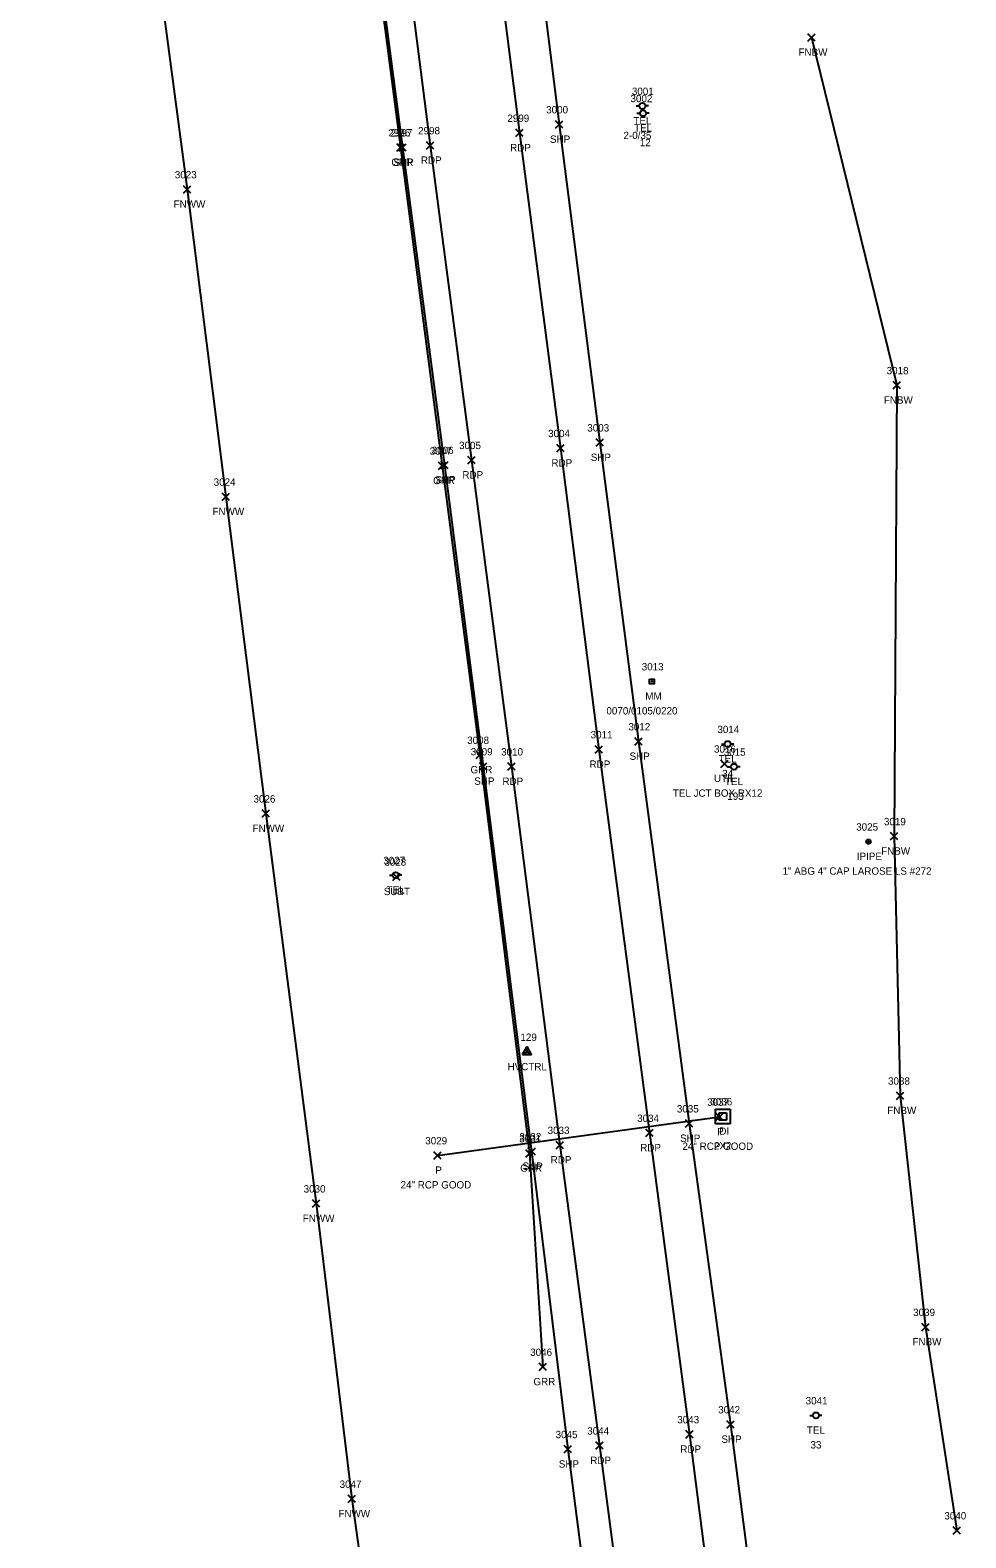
# Model space of a CAD drawing. Extents: x 1443071 to 1445292, y 614024 to 622563.
# Drawn here: x 1444081.8 to 1444336.5, y 617614.4 to 618024.6 of the extents above; entities that cross this region are included whole.
import ezdxf

# ---------------------------------------------------------------- set-up
doc = ezdxf.new("R2010")
doc.units = 0
for name, color, linetype in [('C_A', 7, 'Continuous'), ('C_I', 7, 'Continuous'), ('CPSM', 7, 'Continuous'), ('D_A', 7, 'Continuous'), ('D_C', 7, 'Continuous'), ('D_I', 7, 'Continuous'), ('D_TIC', 7, 'Continuous'), ('DCP', 7, 'Continuous'), ('DS', 7, 'Continuous'), ('L_A', 7, 'Continuous'), ('L_I', 7, 'Continuous'), ('L_TIC', 7, 'Continuous'), ('LFNC', 7, 'Continuous'), ('M_A', 7, 'Continuous'), ('M_C', 7, 'Continuous'), ('M_I', 7, 'Continuous'), ('MPIP', 7, 'Continuous'), ('P_A', 7, 'Continuous'), ('P_I', 7, 'Continuous'), ('P_TIC', 7, 'Continuous'), ('PET', 7, 'Continuous'), ('PSP', 7, 'Continuous'), ('R_A', 7, 'Continuous'), ('R_I', 7, 'Continuous'), ('R_TIC', 7, 'Continuous'), ('RGR', 7, 'Continuous'), ('S_A', 7, 'Continuous'), ('S_C', 7, 'Continuous'), ('S_I', 7, 'Continuous'), ('SRM', 7, 'Continuous'), ('U_A', 7, 'Continuous'), ('U_C', 7, 'Continuous'), ('U_I', 7, 'Continuous'), ('U_TIC', 7, 'Continuous'), ('UDEFAULT', 7, 'Continuous'), ('UP', 7, 'Continuous')]:
    doc.layers.add(name, color=color, linetype=linetype)

msp = doc.modelspace()

# ---------------------------------------------------------------- linework, layer by layer
at = {"layer": 'CPSM'}
for p, q in [((1444215.83, 617745.86), (1444217.08, 617748.02)), ((1444215.83, 617745.86), (1444217.08, 617746.58)), ((1444218.33, 617745.86), (1444217.08, 617748.02)), ((1444217.08, 617746.58), (1444217.08, 617748.02)), ((1444217.08, 617746.58), (1444217.08, 617746.58)), ((1444217.08, 617746.58), (1444218.33, 617745.86)), ((1444215.83, 617745.86), (1444218.33, 617745.86))]:
    msp.add_line(p, q, dxfattribs=at)
at = {"layer": 'D_TIC'}
for points in [[(1444268.44, 617727.93), (1444270.44, 617729.93)], [(1444270.44, 617727.93), (1444268.44, 617729.93)], [(1444191.73, 617717.43), (1444193.73, 617719.43)], [(1444193.73, 617717.43), (1444191.73, 617719.43)]]:
    msp.add_lwpolyline(points, dxfattribs=at)
at = {"layer": 'DCP'}
msp.add_lwpolyline([(1444192.73, 617718.43), (1444269.44, 617728.93)], dxfattribs=at)
at = {"layer": 'DS'}
for p, q in [((1444268.35, 617731.05), (1444272.35, 617731.05)), ((1444268.35, 617727.05), (1444268.35, 617731.05)), ((1444269.35, 617728.05), (1444269.35, 617730.05)), ((1444269.35, 617730.05), (1444271.35, 617730.05)), ((1444271.35, 617730.05), (1444271.35, 617728.05)), ((1444272.35, 617731.05), (1444272.35, 617727.05)), ((1444272.35, 617727.05), (1444268.35, 617727.05)), ((1444271.35, 617728.05), (1444269.35, 617728.05)), ((1444270.35, 617729.05), (1444270.35, 617729.05)), ((1444270.35, 617729.05), (1444270.35, 617729.05))]:
    msp.add_line(p, q, dxfattribs=at)
at = {"layer": 'L_TIC'}
for points in [[(1444293.48, 618021.6), (1444295.48, 618023.6)], [(1444295.48, 618021.6), (1444293.48, 618023.6)], [(1444123.56, 617980.26), (1444125.56, 617982.26)], [(1444125.56, 617980.26), (1444123.56, 617982.26)], [(1444316.71, 617926.96), (1444318.71, 617928.96)], [(1444318.71, 617926.96), (1444316.71, 617928.96)], [(1444134.13, 617896.63), (1444136.13, 617898.63)], [(1444136.13, 617896.63), (1444134.13, 617898.63)], [(1444145.03, 617810.43), (1444147.03, 617812.43)], [(1444147.03, 617810.43), (1444145.03, 617812.43)], [(1444315.98, 617804.26), (1444317.98, 617806.26)], [(1444317.98, 617804.26), (1444315.98, 617806.26)], [(1444317.65, 617733.67), (1444319.65, 617735.67)], [(1444319.65, 617733.67), (1444317.65, 617735.67)], [(1444158.7, 617704.33), (1444160.7, 617706.33)], [(1444160.7, 617704.33), (1444158.7, 617706.33)], [(1444324.49, 617670.72), (1444326.49, 617672.72)], [(1444326.49, 617670.72), (1444324.49, 617672.72)], [(1444168.41, 617623.98), (1444170.41, 617625.98)], [(1444170.41, 617623.98), (1444168.41, 617625.98)], [(1444333.07, 617615.38), (1444335.07, 617617.38)], [(1444335.07, 617615.38), (1444333.07, 617617.38)]]:
    msp.add_lwpolyline(points, dxfattribs=at)
at = {"layer": 'LFNC'}
for points in [[(1444083.93, 618296.19), (1444095.32, 618214.33), (1444111.27, 618081.76), (1444124.56, 617981.26), (1444135.13, 617897.63), (1444146.03, 617811.43), (1444159.7, 617705.33), (1444169.41, 617624.98), (1444181.16, 617539.76), (1444195.37, 617437.22), (1444201.1, 617394.69), (1444208.54, 617337.83), (1444221.64, 617239.47)], [(1444294.48, 618022.6), (1444317.71, 617927.96), (1444316.98, 617805.26), (1444318.65, 617734.67), (1444325.49, 617671.72), (1444334.07, 617616.38)]]:
    msp.add_lwpolyline(points, dxfattribs=at)
at = {"layer": 'MPIP'}
for radius in [0.625, 0.0833]:
    msp.add_circle((1444309.99, 617803.8), radius, dxfattribs=at)
at = {"layer": 'P_TIC'}
for points in [[(1444213.98, 617995.62), (1444215.98, 617997.62)], [(1444215.98, 617995.62), (1444213.98, 617997.62)], [(1444224.79, 617997.93), (1444226.79, 617999.93)], [(1444226.79, 617997.93), (1444224.79, 617999.93)], [(1444182.2, 617991.65), (1444184.2, 617993.65)], [(1444184.2, 617991.65), (1444182.2, 617993.65)], [(1444189.69, 617992.23), (1444191.69, 617994.23)], [(1444191.69, 617992.23), (1444189.69, 617994.23)], [(1444225.22, 617909.85), (1444227.22, 617911.85)], [(1444227.22, 617909.85), (1444225.22, 617911.85)], [(1444235.89, 617911.38), (1444237.89, 617913.38)], [(1444237.89, 617911.38), (1444235.89, 617913.38)], [(1444193.59, 617905.27), (1444195.59, 617907.27)], [(1444195.59, 617905.27), (1444193.59, 617907.27)], [(1444201, 617906.6), (1444203, 617908.6)], [(1444203, 617906.6), (1444201, 617908.6)], [(1444235.58, 617827.89), (1444237.58, 617829.89)], [(1444237.58, 617827.89), (1444235.58, 617829.89)], [(1444246.43, 617830.06), (1444248.43, 617832.06)], [(1444248.43, 617830.06), (1444246.43, 617832.06)], [(1444204.17, 617823.27), (1444206.17, 617825.27)], [(1444206.17, 617823.27), (1444204.17, 617825.27)], [(1444211.88, 617823.23), (1444213.88, 617825.23)], [(1444213.88, 617823.23), (1444211.88, 617825.23)], [(1444260.19, 617726.11), (1444262.19, 617728.11)], [(1444262.19, 617726.11), (1444260.19, 617728.11)], [(1444225.02, 617720.24), (1444227.02, 617722.24)], [(1444227.02, 617720.24), (1444225.02, 617722.24)], [(1444249.39, 617723.54), (1444251.39, 617725.54)], [(1444251.39, 617723.54), (1444249.39, 617725.54)], [(1444217.33, 617718.51), (1444219.33, 617720.51)], [(1444219.33, 617718.51), (1444217.33, 617720.51)], [(1444271.44, 617644.23), (1444273.44, 617646.23)], [(1444273.44, 617644.23), (1444271.44, 617646.23)], [(1444235.79, 617638.47), (1444237.79, 617640.47)], [(1444237.79, 617638.47), (1444235.79, 617640.47)], [(1444260.29, 617641.54), (1444262.29, 617643.54)], [(1444262.29, 617641.54), (1444260.29, 617643.54)], [(1444227.19, 617637.49), (1444229.19, 617639.49)], [(1444229.19, 617637.49), (1444227.19, 617639.49)]]:
    msp.add_lwpolyline(points, dxfattribs=at)
at = {"layer": 'PET'}
for points in [[(1444109.49, 618620.85), (1444119.47, 618545.62), (1444130.61, 618455.68), (1444144.21, 618352.46), (1444156.88, 618257.4), (1444168.48, 618168.47), (1444177.52, 618096.27), (1444190.69, 617993.23), (1444202, 617907.6), (1444212.88, 617824.23), (1444226.02, 617721.24), (1444236.79, 617639.47), (1444249.46, 617542.71), (1444261.59, 617448.18), (1444272.05, 617365.11), (1444281.69, 617294.39), (1444290.04, 617226.49), (1444293.29, 617200.68)], [(1444134.15, 618623.05), (1444144.16, 618546.64), (1444155.44, 618457.71), (1444168.74, 618355.37), (1444181.06, 618259.94), (1444192.98, 618171.23), (1444202.29, 618096.22), (1444214.98, 617996.62), (1444226.22, 617910.85), (1444236.58, 617828.89), (1444250.39, 617724.54), (1444261.29, 617642.54), (1444273.75, 617545.2), (1444286.2, 617451.52), (1444296.55, 617367.39), (1444306.03, 617297.15), (1444314.9, 617227.6), (1444331.28, 617099.37)]]:
    msp.add_lwpolyline(points, dxfattribs=at)
at = {"layer": 'PSP'}
for points in [[(1444144.78, 618624.26), (1444154.69, 618549.98), (1444166.36, 618458.69), (1444180.45, 618353.82), (1444192.35, 618260.76), (1444204.1, 618173.53), (1444213.61, 618097.19), (1444225.79, 617998.93), (1444236.89, 617912.38), (1444247.43, 617831.06), (1444261.19, 617727.11), (1444272.44, 617645.23), (1444285.85, 617541.72), (1444291.35, 617497.66), (1444296.98, 617453.39), (1444307.66, 617368.49), (1444316.83, 617299.16), (1444325.72, 617229.34), (1444331.18, 617190.03)], [(1444101.61, 618620.44), (1444111.35, 618544.8), (1444122.98, 618455.4), (1444136.42, 618350.98), (1444148.78, 618256.45), (1444160.51, 618166.98), (1444169.64, 618095.48), (1444183.2, 617992.65), (1444194.59, 617906.27), (1444205.17, 617824.27), (1444218.33, 617719.51), (1444228.19, 617638.49), (1444240.73, 617541.32), (1444252.82, 617447.41), (1444262.81, 617364.65), (1444271.65, 617293.61), (1444280.5, 617226.12), (1444283.66, 617200.61)]]:
    msp.add_lwpolyline(points, dxfattribs=at)
at = {"layer": 'R_TIC'}
for points in [[(1444181.66, 617991.67), (1444183.66, 617993.67)], [(1444183.66, 617991.67), (1444181.66, 617993.67)], [(1444193.01, 617905.07), (1444195.01, 617907.07)], [(1444195.01, 617905.07), (1444193.01, 617907.07)], [(1444203.2, 617826.38), (1444205.2, 617828.38)], [(1444205.2, 617826.38), (1444203.2, 617828.38)], [(1444216.72, 617717.99), (1444218.72, 617719.99)], [(1444218.72, 617717.99), (1444216.72, 617719.99)], [(1444220.33, 617659.88), (1444222.33, 617661.88)], [(1444222.33, 617659.88), (1444220.33, 617661.88)]]:
    msp.add_lwpolyline(points, dxfattribs=at)
at = {"layer": 'RGR'}
msp.add_lwpolyline([(1444081.85, 618739.61), (1444090.02, 618703.1), (1444100.8, 618620.43), (1444110.62, 618544.53), (1444122.19, 618455.29), (1444135.7, 618350.74), (1444148.14, 618256.46), (1444159.76, 618166.72), (1444169.23, 618095.42), (1444182.66, 617992.67), (1444194.01, 617906.07), (1444204.2, 617827.38), (1444217.72, 617718.99), (1444221.33, 617660.88)], dxfattribs=at)
at = {"layer": 'SRM'}
msp.add_lwpolyline([(1444250.44, 617848.03), (1444251.69, 617848.03), (1444251.69, 617846.78), (1444250.44, 617846.78)], close=True, dxfattribs=at)
msp.add_circle((1444251.07, 617847.4), 0.0833, dxfattribs=at)
at = {"layer": 'U_TIC'}
for points in [[(1444180.58, 617793.25), (1444182.58, 617795.25)], [(1444182.58, 617793.25), (1444180.58, 617795.25)]]:
    msp.add_lwpolyline(points, dxfattribs=at)
at = {"layer": 'UDEFAULT'}
for points in [[(1444269.78, 617824.01), (1444271.78, 617826.01)], [(1444271.78, 617824.01), (1444269.78, 617826.01)]]:
    msp.add_lwpolyline(points, dxfattribs=at)
at = {"layer": 'UP'}
for p, q in [((1444246.79, 618003.95), (1444247.62, 618003.95)), ((1444246.99, 618001.99), (1444247.82, 618001.99)), ((1444248.45, 618003.95), (1444248.45, 618003.95)), ((1444248.65, 618001.99), (1444248.65, 618001.99)), ((1444250.12, 618003.95), (1444249.29, 618003.95)), ((1444249.29, 618003.95), (1444249.29, 618003.95)), ((1444250.32, 618001.99), (1444249.48, 618001.99)), ((1444249.48, 618001.99), (1444249.48, 618001.99)), ((1444250.12, 618003.95), (1444250.12, 618003.95)), ((1444250.32, 618001.99), (1444250.32, 618001.99)), ((1444269.99, 617830.32), (1444270.81, 617830.32)), ((1444271.65, 617830.33), (1444271.65, 617830.33)), ((1444273.31, 617830.33), (1444272.48, 617830.33)), ((1444272.48, 617830.33), (1444272.48, 617830.33)), ((1444273.31, 617830.33), (1444273.31, 617830.33)), ((1444271.72, 617824.17), (1444272.54, 617824.17)), ((1444273.38, 617824.17), (1444273.38, 617824.17)), ((1444275.04, 617824.17), (1444274.21, 617824.17)), ((1444274.21, 617824.17), (1444274.21, 617824.17)), ((1444275.04, 617824.17), (1444275.04, 617824.17)), ((1444179.65, 617794.66), (1444180.47, 617794.66)), ((1444181.31, 617794.67), (1444181.31, 617794.67)), ((1444182.97, 617794.67), (1444182.14, 617794.67)), ((1444182.14, 617794.67), (1444182.14, 617794.67)), ((1444182.97, 617794.67), (1444182.97, 617794.67)), ((1444294.01, 617647.69), (1444294.84, 617647.69)), ((1444295.67, 617647.69), (1444295.67, 617647.69)), ((1444297.34, 617647.69), (1444296.5, 617647.69)), ((1444296.5, 617647.69), (1444296.5, 617647.69)), ((1444297.34, 617647.69), (1444297.34, 617647.69))]:
    msp.add_line(p, q, dxfattribs=at)
for centre in [(1444248.45, 618003.95), (1444248.65, 618001.99), (1444271.65, 617830.33), (1444273.38, 617824.17), (1444181.31, 617794.67), (1444295.67, 617647.69)]:
    msp.add_circle(centre, 0.833, dxfattribs=at)

# ---------------------------------------------------------------- texts
at = {"layer": 'C_A'}
msp.add_text('HVCTRL', height=2, dxfattribs=at).set_placement((1444211.77, 617741.58))
at = {"layer": 'C_I'}
msp.add_text('129', height=2, dxfattribs=at).set_placement((1444215.27, 617749.58))
at = {"layer": 'D_A'}
for s, p in [('P', (1444268.82, 617723.93)), ('DI', (1444269.41, 617724.05)), ('P', (1444192.11, 617713.43))]:
    msp.add_text(s, height=2, dxfattribs=at).set_placement(p)
at = {"layer": 'D_C'}
for s, p in [('24" RCP GOOD', (1444259.37, 617719.93)), ('2X2', (1444267.93, 617720.05)), ('24" RCP GOOD', (1444182.66, 617709.43))]:
    msp.add_text(s, height=2, dxfattribs=at).set_placement(p)
at = {"layer": 'D_I'}
for s, p in [('3036', (1444266.96, 617732.05)), ('3037', (1444266.1, 617731.93)), ('3029', (1444189.38, 617721.43))]:
    msp.add_text(s, height=2, dxfattribs=at).set_placement(p)
at = {"layer": 'L_A'}
for s, p in [('FNBW', (1444290.95, 618017.6)), ('FNWW', (1444120.91, 617976.26)), ('FNBW', (1444314.18, 617922.96)), ('FNWW', (1444131.48, 617892.63)), ('FNWW', (1444142.37, 617806.43)), ('FNBW', (1444313.45, 617800.26)), ('FNBW', (1444315.12, 617729.67)), ('FNWW', (1444156.04, 617700.33)), ('FNBW', (1444321.97, 617666.72)), ('FNWW', (1444165.75, 617619.98))]:
    msp.add_text(s, height=2, dxfattribs=at).set_placement(p)
at = {"layer": 'L_I'}
for s, p in [('3023', (1444121.22, 617984.26)), ('3018', (1444314.94, 617930.96)), ('3024', (1444131.79, 617900.63)), ('3026', (1444142.63, 617814.43)), ('3019', (1444314.2, 617808.26)), ('3038', (1444315.31, 617737.67)), ('3030', (1444156.27, 617708.33)), ('3039', (1444322.15, 617674.72)), ('3047', (1444166.07, 617627.98)), ('3040', (1444330.65, 617619.38))]:
    msp.add_text(s, height=2, dxfattribs=at).set_placement(p)
at = {"layer": 'M_A'}
msp.add_text('IPIPE', height=2, dxfattribs=at).set_placement((1444306.82, 617798.8))
at = {"layer": 'M_C'}
msp.add_text('1" ABG 4" CAP LAROSE LS #272', height=2, dxfattribs=at).set_placement((1444286.6, 617794.8))
at = {"layer": 'M_I'}
msp.add_text('3025', height=2, dxfattribs=at).set_placement((1444306.65, 617806.8))
at = {"layer": 'P_A'}
for s, p in [('RDP', (1444212.47, 617991.62)), ('SHP', (1444223.32, 617993.93)), ('SHP', (1444180.73, 617987.65)), ('RDP', (1444188.18, 617988.23)), ('RDP', (1444223.71, 617905.85)), ('SHP', (1444234.42, 617907.38)), ('SHP', (1444192.13, 617901.27)), ('RDP', (1444199.48, 617902.6)), ('RDP', (1444234.07, 617823.89)), ('SHP', (1444244.97, 617826.06)), ('SHP', (1444202.71, 617819.27)), ('RDP', (1444210.37, 617819.23)), ('SHP', (1444258.73, 617722.11)), ('RDP', (1444223.5, 617716.24)), ('RDP', (1444247.88, 617719.54)), ('SHP', (1444215.86, 617714.51)), ('SHP', (1444269.97, 617640.23)), ('SHP', (1444225.72, 617633.49)), ('RDP', (1444234.28, 617634.47)), ('RDP', (1444258.78, 617637.54))]:
    msp.add_text(s, height=2, dxfattribs=at).set_placement(p)
at = {"layer": 'P_I'}
for s, p in [('2999', (1444211.72, 617999.62)), ('3000', (1444222.28, 618001.93)), ('2997', (1444179.94, 617995.65)), ('2998', (1444187.43, 617996.23)), ('3004', (1444222.81, 617913.85)), ('3003', (1444233.47, 617915.38)), ('3006', (1444191.12, 617909.27)), ('3005', (1444198.58, 617910.6)), ('3011', (1444234.38, 617831.89)), ('3012', (1444244.66, 617834.06)), ('3009', (1444201.75, 617827.27)), ('3010', (1444210.02, 617827.23)), ('3035', (1444257.85, 617730.11)), ('3033', (1444222.68, 617724.24)), ('3034', (1444247.05, 617727.54)), ('3032', (1444214.99, 617722.51)), ('3042', (1444269.1, 617648.23)), ('3044', (1444233.46, 617642.47)), ('3043', (1444257.96, 617645.54)), ('3045', (1444224.85, 617641.49))]:
    msp.add_text(s, height=2, dxfattribs=at).set_placement(p)
at = {"layer": 'R_A'}
for p in [(1444180.15, 617987.67), (1444191.5, 617901.07), (1444201.69, 617822.38), (1444215.21, 617713.99), (1444218.81, 617655.88)]:
    msp.add_text('GRR', height=2, dxfattribs=at).set_placement(p)
at = {"layer": 'R_I'}
for s, p in [('2996', (1444179.34, 617995.67)), ('3007', (1444190.59, 617909.07)), ('3008', (1444200.78, 617830.38)), ('3031', (1444214.95, 617721.99)), ('3046', (1444217.93, 617663.88))]:
    msp.add_text(s, height=2, dxfattribs=at).set_placement(p)
at = {"layer": 'S_A'}
msp.add_text('MM', height=2, dxfattribs=at).set_placement((1444249.26, 617842.4))
at = {"layer": 'S_C'}
msp.add_text('0070/0105/0220', height=2, dxfattribs=at).set_placement((1444238.68, 617838.4))
at = {"layer": 'S_I'}
msp.add_text('3013', height=2, dxfattribs=at).set_placement((1444248.29, 617850.4))
at = {"layer": 'U_A'}
for s, p in [('TEL', (1444246.01, 617998.95)), ('TEL', (1444246.21, 617996.99)), ('TEL', (1444269.21, 617825.33)), ('UTIL', (1444267.94, 617820.01)), ('TEL', (1444270.93, 617819.17)), ('TEL', (1444178.87, 617789.67)), ('SUBT', (1444178.08, 617789.25)), ('TEL', (1444293.23, 617642.69))]:
    msp.add_text(s, height=2, dxfattribs=at).set_placement(p)
at = {"layer": 'U_C'}
for s, p in [('2-0/35', (1444243.32, 617994.95)), ('12', (1444247.75, 617992.99)), ('34', (1444270.18, 617821.33)), ('TEL JCT BOX RX12', (1444256.75, 617816.01)), ('193', (1444271.58, 617815.17)), ('33', (1444294.21, 617638.69))]:
    msp.add_text(s, height=2, dxfattribs=at).set_placement(p)
at = {"layer": 'U_I'}
for s, p in [('3001', (1444245.6, 618006.95)), ('3002', (1444245.23, 618004.99)), ('3014', (1444268.88, 617833.33)), ('3016', (1444267.95, 617828.01)), ('3015', (1444270.6, 617827.17)), ('3027', (1444177.97, 617797.67)), ('3028', (1444178.24, 617797.25)), ('3041', (1444292.9, 617650.69))]:
    msp.add_text(s, height=2, dxfattribs=at).set_placement(p)

doc.saveas('drawing.dxf')
